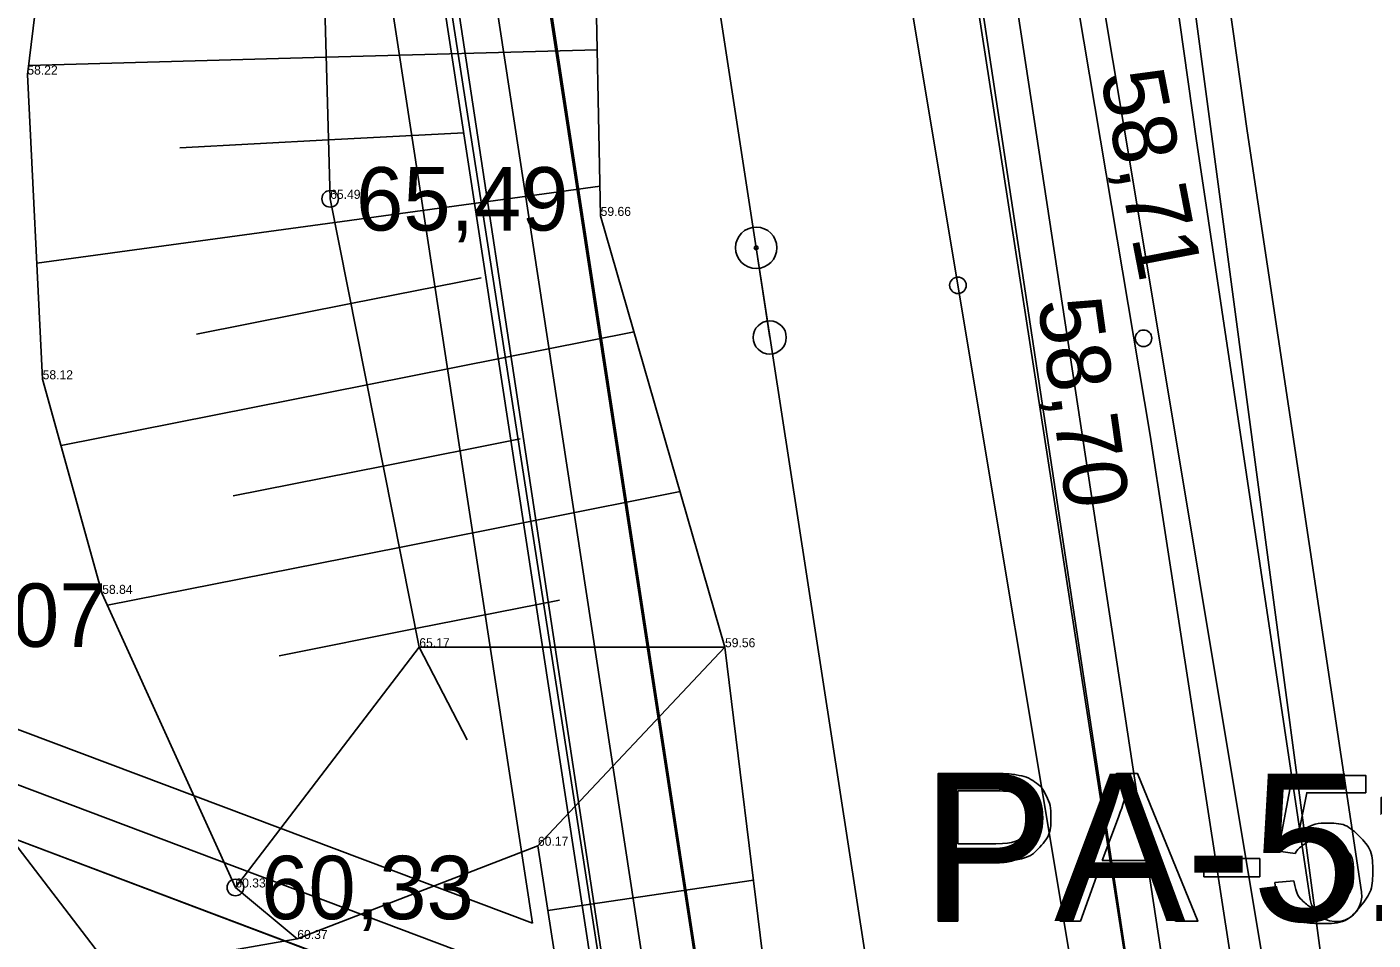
# Model space of a CAD drawing. Extents: x 700746 to 706058, y 6570320 to 6580460.
# Drawn here: x 703268 to 703320, y 6576965.6 to 6577000.9 of the extents above; entities that cross this region are included whole.
import ezdxf

# ---------------------------------------------------------------- set-up
doc = ezdxf.new("R2010")
doc.units = 0
for name, color, linetype in [('GEOLPUNKT', 7, 'Continuous'), ('illumineerimisjooned', 7, 'Continuous'), ('Kaitsevöönd', 7, 'Continuous'), ('kataster', 7, 'Continuous'), ('KORGUS-EH2000', 7, 'Continuous'), ('KPOHULIIN', 7, 'Continuous'), ('maeeraldised_kehtivad', 7, 'Continuous'), ('MOOTKORG-EH2000', 7, 'Continuous'), ('Plokid', 7, 'Continuous'), ('POST', 7, 'Continuous'), ('RELJEEF', 7, 'Continuous'), ('TEE', 7, 'Continuous'), ('Tmaad_maeeraldised_kehtivad', 7, 'Continuous'), ('VTRASS', 7, 'Continuous'), ('VWX2_MV_PLOKK', 7, 'Continuous')]:
    doc.layers.add(name, color=color, linetype=linetype)

msp = doc.modelspace()

# ---------------------------------------------------------------- linework, layer by layer
at = {"layer": 'GEOLPUNKT'}
for points in [[(703303.208, 6576966.311), (703303.208, 6576972.011), (703305.36, 6576972.011)], [(703307.9, 6576966.311), (703310.09, 6576972.011), (703310.907, 6576972.011), (703313.235, 6576966.311), (703312.375, 6576966.311), (703311.715, 6576968.036), (703309.324, 6576968.036), (703308.7, 6576966.311), (703307.9, 6576966.311)], [(703316.985, 6576968.922), (703316.329, 6576969.009), (703316.881, 6576971.937), (703319.713, 6576971.937), (703319.713, 6576971.268), (703317.44, 6576971.268), (703317.133, 6576969.738)], [(703305.423, 6576971.338), (703303.964, 6576971.338), (703303.964, 6576969.3)], [(703310.173, 6576970.323), (703309.543, 6576968.649)], [(703309.543, 6576968.649), (703311.478, 6576968.649), (703310.881, 6576970.231)], [(703303.964, 6576969.3), (703305.438, 6576969.3)], [(703305.427, 6576968.627), (703303.964, 6576968.627), (703303.964, 6576966.311), (703303.208, 6576966.311)], [(703313.47, 6576968.023), (703313.47, 6576968.727), (703315.625, 6576968.727), (703315.625, 6576968.023), (703313.47, 6576968.023)], [(703316.203, 6576967.806), (703316.937, 6576967.867)]]:
    msp.add_lwpolyline(points, dxfattribs=at)
for points in [[(703305.36, 6576972.011), (703305.928, 6576972.011), (703306.227, 6576971.957), (703306.647, 6576971.887), (703306.931, 6576971.69), (703307.215, 6576971.494), (703307.388, 6576971.14), (703307.562, 6576970.786), (703307.562, 6576970.362), (703307.562, 6576969.634), (703307.099, 6576969.131), (703306.636, 6576968.627), (703305.427, 6576968.627)], [(703305.438, 6576969.3), (703306.169, 6576969.3), (703306.477, 6576969.573), (703306.784, 6576969.845), (703306.784, 6576970.338), (703306.784, 6576970.696), (703306.603, 6576970.951), (703306.422, 6576971.206), (703306.127, 6576971.287), (703305.936, 6576971.338), (703305.423, 6576971.338)], [(703310.881, 6576970.231), (703310.613, 6576970.952), (703310.479, 6576971.412), (703310.366, 6576970.865), (703310.173, 6576970.323)], [(703317.133, 6576969.738), (703317.646, 6576970.095), (703318.21, 6576970.095), (703318.956, 6576970.095), (703319.469, 6576969.578), (703319.983, 6576969.06), (703319.983, 6576968.247), (703319.983, 6576967.473), (703319.531, 6576966.908), (703318.983, 6576966.216), (703318.034, 6576966.216), (703317.257, 6576966.216), (703316.765, 6576966.651), (703316.273, 6576967.087), (703316.203, 6576967.806)], [(703316.937, 6576967.867), (703317.019, 6576967.33), (703317.315, 6576967.06), (703317.612, 6576966.789), (703318.034, 6576966.789), (703318.543, 6576966.789), (703318.891, 6576967.171), (703319.24, 6576967.553), (703319.24, 6576968.184), (703319.24, 6576968.785), (703318.905, 6576969.132), (703318.57, 6576969.478), (703318.023, 6576969.478), (703317.682, 6576969.478), (703317.411, 6576969.324), (703317.14, 6576969.169), (703316.985, 6576968.922)]]:
    msp.add_open_spline(points, degree=3, dxfattribs=at)
at = {"layer": 'illumineerimisjooned'}
for points in [[(702976.891, 6576643.26), (702915.328, 6577059.558), (702785.772, 6577104.455), (702748.407, 6577249.47), (702721.642, 6577298.043), (702716.252, 6577332.033), (702861.102, 6577284.56), (703066.328, 6577217.365), (703088.858, 6577210.018), (703169.031, 6577150.466), (703230.271, 6577104.95), (703275.453, 6577071.675), (703358.033, 6576531.935)], [(703290.041, 6576963.147), (703188.508, 6577001.438), (703016.934, 6577112.515), (702852.033, 6577230.395), (702862.776, 6577281.723), (703065.707, 6577215.464), (703087.928, 6577208.218), (703167.838, 6577148.861), (703229.081, 6577103.342), (703273.601, 6577070.555), (703290.041, 6576963.147)]]:
    msp.add_lwpolyline(points, dxfattribs=at)
at = {"layer": 'Kaitsevöönd'}
for points in [[(703332.065, 6576694.743), (703304.442, 6576872.638), (703273.694, 6577070.52), (703230.233, 6577104.832), (703217.52, 6577108.973), (703142.719, 6577173.75), (703139.166, 6577177.33), (703138.297, 6577181.096), (703138.49, 6577185.153), (703140.421, 6577188.437), (703144.379, 6577190.851), (703147.661, 6577191.817), (703151.812, 6577191.141), (703154.805, 6577189.403), (703166.583, 6577179.261), (703228.658, 6577126.14), (703241.595, 6577121.215), (703289.275, 6577083.661), (703291.813, 6577080.846), (703293.137, 6577077.314), (703294.406, 6577068.373), (703355.652, 6576672.76)], [(703154.91, 6577189.152), (703230.532, 6577125.647), (703239.404, 6577123.376), (703292.869, 6577081.186), (703317.705, 6576917.046)], [(703317.705, 6576917.046), (703292.869, 6577081.186), (703239.404, 6577123.376), (703230.532, 6577125.647), (703154.91, 6577189.152)], [(703297.93, 6576914.054), (703274.276, 6577070.381), (703230.34, 6577105.051), (703221.159, 6577107.401), (703142.048, 6577173.836)], [(703142.048, 6577173.836), (703221.159, 6577107.401), (703230.34, 6577105.051), (703274.276, 6577070.381), (703297.93, 6576914.054)], [(703303.575, 6577062.05), (703310.1, 6577032.568), (703315.143, 6576996.833), (703319.551, 6576967.437)], [(703317.573, 6576967.14), (703313.164, 6576996.545), (703308.131, 6577032.212), (703301.642, 6577061.531)], [(703300.31, 6577050.948), (703311.399, 6576985.078), (703330.432, 6576861.446), (703341.024, 6576780.184), (703353.272, 6576691.805)]]:
    msp.add_lwpolyline(points, dxfattribs=at)
msp.add_arc((703318.562, 6576967.289), 1, 188.5272, 8.5272, dxfattribs=at)
at = {"layer": 'kataster'}
msp.add_lwpolyline([(703360.09, 6576531.99), (703277.36, 6577072.83), (703167.04, 6577172.32), (703125.43, 6577441.71), (702859.8, 6577465.72), (702862.38, 6577440.12), (702863.2, 6577375.41), (702851.4, 6577379.23), (702839.86, 6577381.59), (702831.19, 6577380.43), (702820.1, 6577376.69), (702754.28, 6577347.92), (702741.83, 6577344.92), (702732.67, 6577344.2), (702712.5, 6577346.91), (702704.73, 6577347.96), (702701.8, 6577345.85), (702700.78, 6577341.43), (702712.4, 6577226.51), (702651.69, 6577159.42), (702595.69, 6577121.68), (702628.71, 6576895.25), (702720.42, 6576547.28)], dxfattribs=at)
msp.add_lwpolyline([(702852.27, 6575508.89), (702837.26, 6575620.73), (702848.38, 6575976.59), (702782.85, 6576063.35), (702782.57, 6576096.37), (702842.53, 6576210.56), (702853.4, 6576267.5), (702844.46, 6576489.93), (702877.29, 6576548.25), (702974.72, 6576643.9), (702913.57, 6577058.07), (702784.04, 6577102.84), (702746.48, 6577248.7), (702719.69, 6577297.36), (702713.81, 6577334.91), (703089.87, 6577211.79), (703231.53, 6577106.55), (703277.36, 6577072.83), (703360.09, 6576531.99), (703311.6, 6576228.52), (703293.62, 6575965.66), (703298.84, 6575573.29)], close=True, dxfattribs=at)
at = {"layer": 'KORGUS-EH2000'}
for centre in [(703279.74, 6576994.21), (703303.971, 6576990.87), (703311.137, 6576988.824), (703276.08, 6576967.61)]:
    msp.add_circle(centre, 0.32, dxfattribs=at)
at = {"layer": 'KPOHULIIN'}
msp.add_lwpolyline([(703348.189, 6576656.261), (703310.089, 6576902.121), (703296.185, 6576992.32), (703283.369, 6577075.688)], dxfattribs=at)
at = {"layer": 'maeeraldised_kehtivad'}
msp.add_lwpolyline([(702849.808, 6577229.527), (702861.724, 6577286.461), (703066.949, 6577219.266), (703089.789, 6577211.819), (703170.224, 6577152.072), (703231.46, 6577106.558), (703277.305, 6577072.795), (703294.683, 6576959.259), (703187.602, 6576999.642), (703015.809, 6577110.861)], close=True, dxfattribs=at)
at = {"layer": 'Plokid'}
msp.add_line((703296.172, 6577067.83), (703382.069, 6576503.627), dxfattribs=at)
msp.add_lwpolyline([(703287.547, 6576966.226), (703189.415, 6577003.234), (703018.06, 6577114.169), (702854.258, 6577231.263), (702863.9, 6577277.331), (703064.465, 6577211.662), (703086.067, 6577204.618), (703165.453, 6577145.65), (703226.702, 6577100.127), (703272.178, 6577066.636)], close=True, dxfattribs=at)
at = {"layer": 'POST'}
msp.add_line((703296.185, 6576992.32), (703296.707, 6576988.857), dxfattribs=at)
for centre, radius in [((703296.185, 6576992.32), 0.8), ((703296.185, 6576992.32), 0.0747), ((703296.707, 6576988.857), 0.64)]:
    msp.add_circle(centre, radius, dxfattribs=at)
at = {"layer": 'RELJEEF'}
for p, q in [((703279.589, 6576999.683), (703290.051, 6576999.972)), ((703279.589, 6576999.683), (703268.094, 6576999.366)), ((703273.942, 6576996.187), (703279.677, 6576996.485)), ((703284.894, 6576996.756), (703279.677, 6576996.485)), ((703279.92, 6576993.303), (703290.157, 6576994.705)), ((703279.92, 6576993.303), (703268.415, 6576991.727)), ((703285.562, 6576991.161), (703280.543, 6576990.165)), ((703274.578, 6576988.98), (703280.543, 6576990.165)), ((703281.167, 6576987.026), (703291.47, 6576989.072)), ((703281.167, 6576987.026), (703269.351, 6576984.679)), ((703287.075, 6576984.937), (703281.79, 6576983.887)), ((703275.999, 6576982.737), (703281.79, 6576983.887)), ((703282.414, 6576980.749), (703293.248, 6576982.9)), ((703282.414, 6576980.749), (703271.14, 6576978.509)), ((703288.587, 6576978.712), (703283.037, 6576977.61)), ((703277.767, 6576976.563), (703283.037, 6576977.61)), ((703283.18, 6576976.89), (703276.08, 6576967.61)), ((703283.18, 6576976.89), (703294.98, 6576976.89)), ((703283.18, 6576976.89), (703285.025, 6576973.319)), ((703288.142, 6576966.725), (703296.076, 6576967.894))]:
    msp.add_line(p, q, dxfattribs=at)
for points in [[(703273.27, 6577043.56), (703276.36, 6577025.51), (703279.28, 6577010.87), (703279.74, 6576994.21), (703283.18, 6576976.89), (703283.18, 6576976.89)], [(703263.17, 6577042.85), (703266.27, 6577032.5), (703268.54, 6577019.06), (703269.41, 6577010.09), (703268.05, 6576999.01), (703268.64, 6576987.24), (703270.94, 6576978.95), (703276.08, 6576967.61), (703278.47, 6576965.62), (703287.76, 6576969.22)], [(703287.76, 6576969.22), (703294.98, 6576976.89), (703290.18, 6576993.55), (703289.96, 6577004.49), (703284.03, 6577036.79)], [(703294.98, 6576976.89), (703298.009, 6576952.035), (703308.39, 6576903.656), (703310.216, 6576881.633), (703320.055, 6576759.492), (703327.515, 6576726.847), (703331.128, 6576688.396), (703329.023, 6576656.137), (703332.851, 6576644.872), (703338.244, 6576624.531), (703339.694, 6576609.708), (703342.979, 6576573.755), (703350.642, 6576557.993), (703360.73, 6576522.365), (703358.274, 6576513.585), (703356.215, 6576500.078), (703348.179, 6576445.403), (703346.58, 6576371.378), (703340.932, 6576356.928), (703336.907, 6576322.739), (703327.685, 6576295.148), (703320.219, 6576257.656), (703313.499, 6576240.829), (703310.185, 6576232.917)], [(703261.385, 6576968.537), (703266.84, 6576970.24), (703271.343, 6576964.383), (703278.47, 6576965.62)], [(703287.76, 6576969.22), (703301.656, 6576878.366), (703308.402, 6576766.661), (703315.863, 6576734.016), (703319.476, 6576695.565), (703324.84, 6576668.617), (703325.059, 6576655.252), (703326.592, 6576631.7), (703333, 6576614.799), (703334.365, 6576592.701), (703343.184, 6576565.162), (703350.626, 6576529.533), (703350.126, 6576518.579), (703344.563, 6576507.247), (703336.527, 6576452.572), (703334.927, 6576378.547), (703329.28, 6576364.097), (703325.255, 6576329.908), (703316.032, 6576302.316), (703308.567, 6576264.825), (703301.847, 6576247.998), (703298.532, 6576240.086)]]:
    msp.add_lwpolyline(points, dxfattribs=at)
at = {"layer": 'TEE'}
for points in [[(703352.188, 6576141.743), (703333.891, 6576240.908), (703343.285, 6576290.998), (703349.944, 6576325.798), (703355.472, 6576356.506), (703364.509, 6576409.388), (703371.49, 6576445.789), (703377.052, 6576478.468), (703380.318, 6576501.696), (703378.705, 6576535.395), (703372.605, 6576579.277), (703366.542, 6576617.948), (703359.597, 6576660.205), (703326.861, 6576887.215), (703316.48, 6576960.36), (703310.761, 6576994.71), (703303.154, 6577040.421), (703296.055, 6577071.096), (703290.159, 6577081.588), (703186.337, 6577164.979)], [(703345.398, 6576137.903), (703327.102, 6576237.068), (703336.562, 6576290.115), (703343.247, 6576326.507), (703348.807, 6576358.127), (703358.182, 6576409.796), (703364.654, 6576448.177), (703369.91, 6576476.489), (703373.714, 6576502.518), (703371.54, 6576534.249), (703365.816, 6576575.437), (703359.752, 6576614.108), (703352.807, 6576656.365), (703320.071, 6576883.375), (703309.691, 6576956.52), (703303.971, 6576990.87), (703296.365, 6577036.581), (703289.266, 6577067.256), (703283.369, 6577077.748), (703179.547, 6577161.139)]]:
    msp.add_lwpolyline(points, dxfattribs=at)
at = {"layer": 'Tmaad_maeeraldised_kehtivad'}
msp.add_lwpolyline([(702974.764, 6576643.974), (702913.527, 6577058.065), (702784.103, 6577102.917), (702746.534, 6577248.726), (702719.722, 6577297.384), (702713.764, 6577334.953), (702861.724, 6577286.461), (703066.949, 6577219.266), (703089.789, 6577211.819), (703089.789, 6577211.819), (703170.224, 6577152.072), (703231.46, 6577106.558), (703277.305, 6577072.795), (703360.057, 6576531.928)], dxfattribs=at)
at = {"layer": 'VTRASS'}
msp.add_lwpolyline([(703187.298, 6577168.252), (703294.432, 6577085.209), (703301.236, 6577073.103), (703306.844, 6577037.233), (703313.095, 6577001.738), (703318.333, 6576962.356), (703331.426, 6576870.746), (703362.089, 6576663.779), (703368.34, 6576626.426), (703375.774, 6576583.156), (703383.803, 6576538.658), (703383.922, 6576537.608)], dxfattribs=at)
at = {"layer": 'VWX2_MV_PLOKK'}
for points in [[(703044.07, 6577449.05), (703125.37, 6577441.7), (703167.08, 6577172.26), (703170.22, 6577152.1), (703231.53, 6577106.55), (703277.36, 6577072.83), (703360.09, 6576531.99), (703311.6, 6576228.52), (703293.62, 6575965.66), (703294.04, 6575933.77), (703295.43, 6575829.7), (703298.36, 6575609.6), (703298.84, 6575573.29), (703155.29, 6575552.59), (703145.59, 6575981.92), (703123.04, 6576234.88), (703120.61, 6576749.6), (703011.59, 6576989.47), (703015.74, 6577110.88), (702996.73, 6577210.32)], [(702849.88, 6577229.56), (702861.72, 6577286.46), (703066.96, 6577219.29), (703089.79, 6577211.82), (703170.22, 6577152.07), (703231.53, 6577106.55), (703277.36, 6577072.83), (703294.74, 6576959.21), (703187.67, 6576999.67), (703015.74, 6577110.88)], [(702849.88, 6577229.56), (702861.72, 6577286.46), (703066.96, 6577219.29), (703089.79, 6577211.82), (703170.22, 6577152.07), (703231.53, 6577106.55), (703277.36, 6577072.83), (703294.74, 6576959.21), (703187.67, 6576999.67), (703015.74, 6577110.88)], [(703170.54, 6577151.86), (703296.17, 6577067.83), (703382.07, 6576503.63), (703324.97, 6576203.4), (703311.73, 6576015.89), (703294.04, 6575933.77), (703293.62, 6575965.66), (703311.6, 6576228.52), (703360.09, 6576531.99), (703277.36, 6577072.83), (703231.53, 6577106.55)], [(703187.67, 6576999.67), (703294.74, 6576959.21), (703340.88, 6576657.54), (703190.39, 6576656.32)], [(703187.67, 6576999.67), (703294.74, 6576959.21), (703340.88, 6576657.54), (703190.39, 6576656.32)]]:
    msp.add_lwpolyline(points, close=True, dxfattribs=at)

# ---------------------------------------------------------------- texts
at = {"layer": 'GEOLPUNKT'}
msp.add_text('PA-5106', height=5.7, dxfattribs=at).set_placement((703302.596, 6576966.311))
at = {"layer": 'KORGUS-EH2000'}
for s, rotation, p in [('58,71 ', 280.9179, (703309.462, 6576998.992)), ('58,70 ', 277.9759, (703307.045, 6576990.255))]:
    msp.add_text(s, height=2.45, rotation=rotation, dxfattribs=at).set_placement(p)
for s, p in [('65,49', (703280.74, 6576992.985)), ('60,07', (703262.903, 6576976.904)), ('60,33', (703277.08, 6576966.385))]:
    msp.add_text(s, height=2.45, dxfattribs=at).set_placement(p)
at = {"layer": 'MOOTKORG-EH2000'}
for s, p in [('58.22', (703268.05, 6576999.01)), ('65.49', (703279.74, 6576994.21)), ('59.66', (703290.18, 6576993.55)), ('58.12', (703268.64, 6576987.24)), ('58.84', (703270.94, 6576978.95)), ('65.17', (703283.18, 6576976.89)), ('59.56', (703294.98, 6576976.89)), ('60.17', (703287.76, 6576969.22)), ('60.33', (703276.08, 6576967.61)), ('60.37', (703278.47, 6576965.62))]:
    msp.add_text(s, height=0.35, dxfattribs=at).set_placement(p)

doc.saveas('drawing.dxf')
